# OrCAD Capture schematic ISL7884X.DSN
size B; title: ISL7884X Application Circuit Transient Test; note: <Doc>
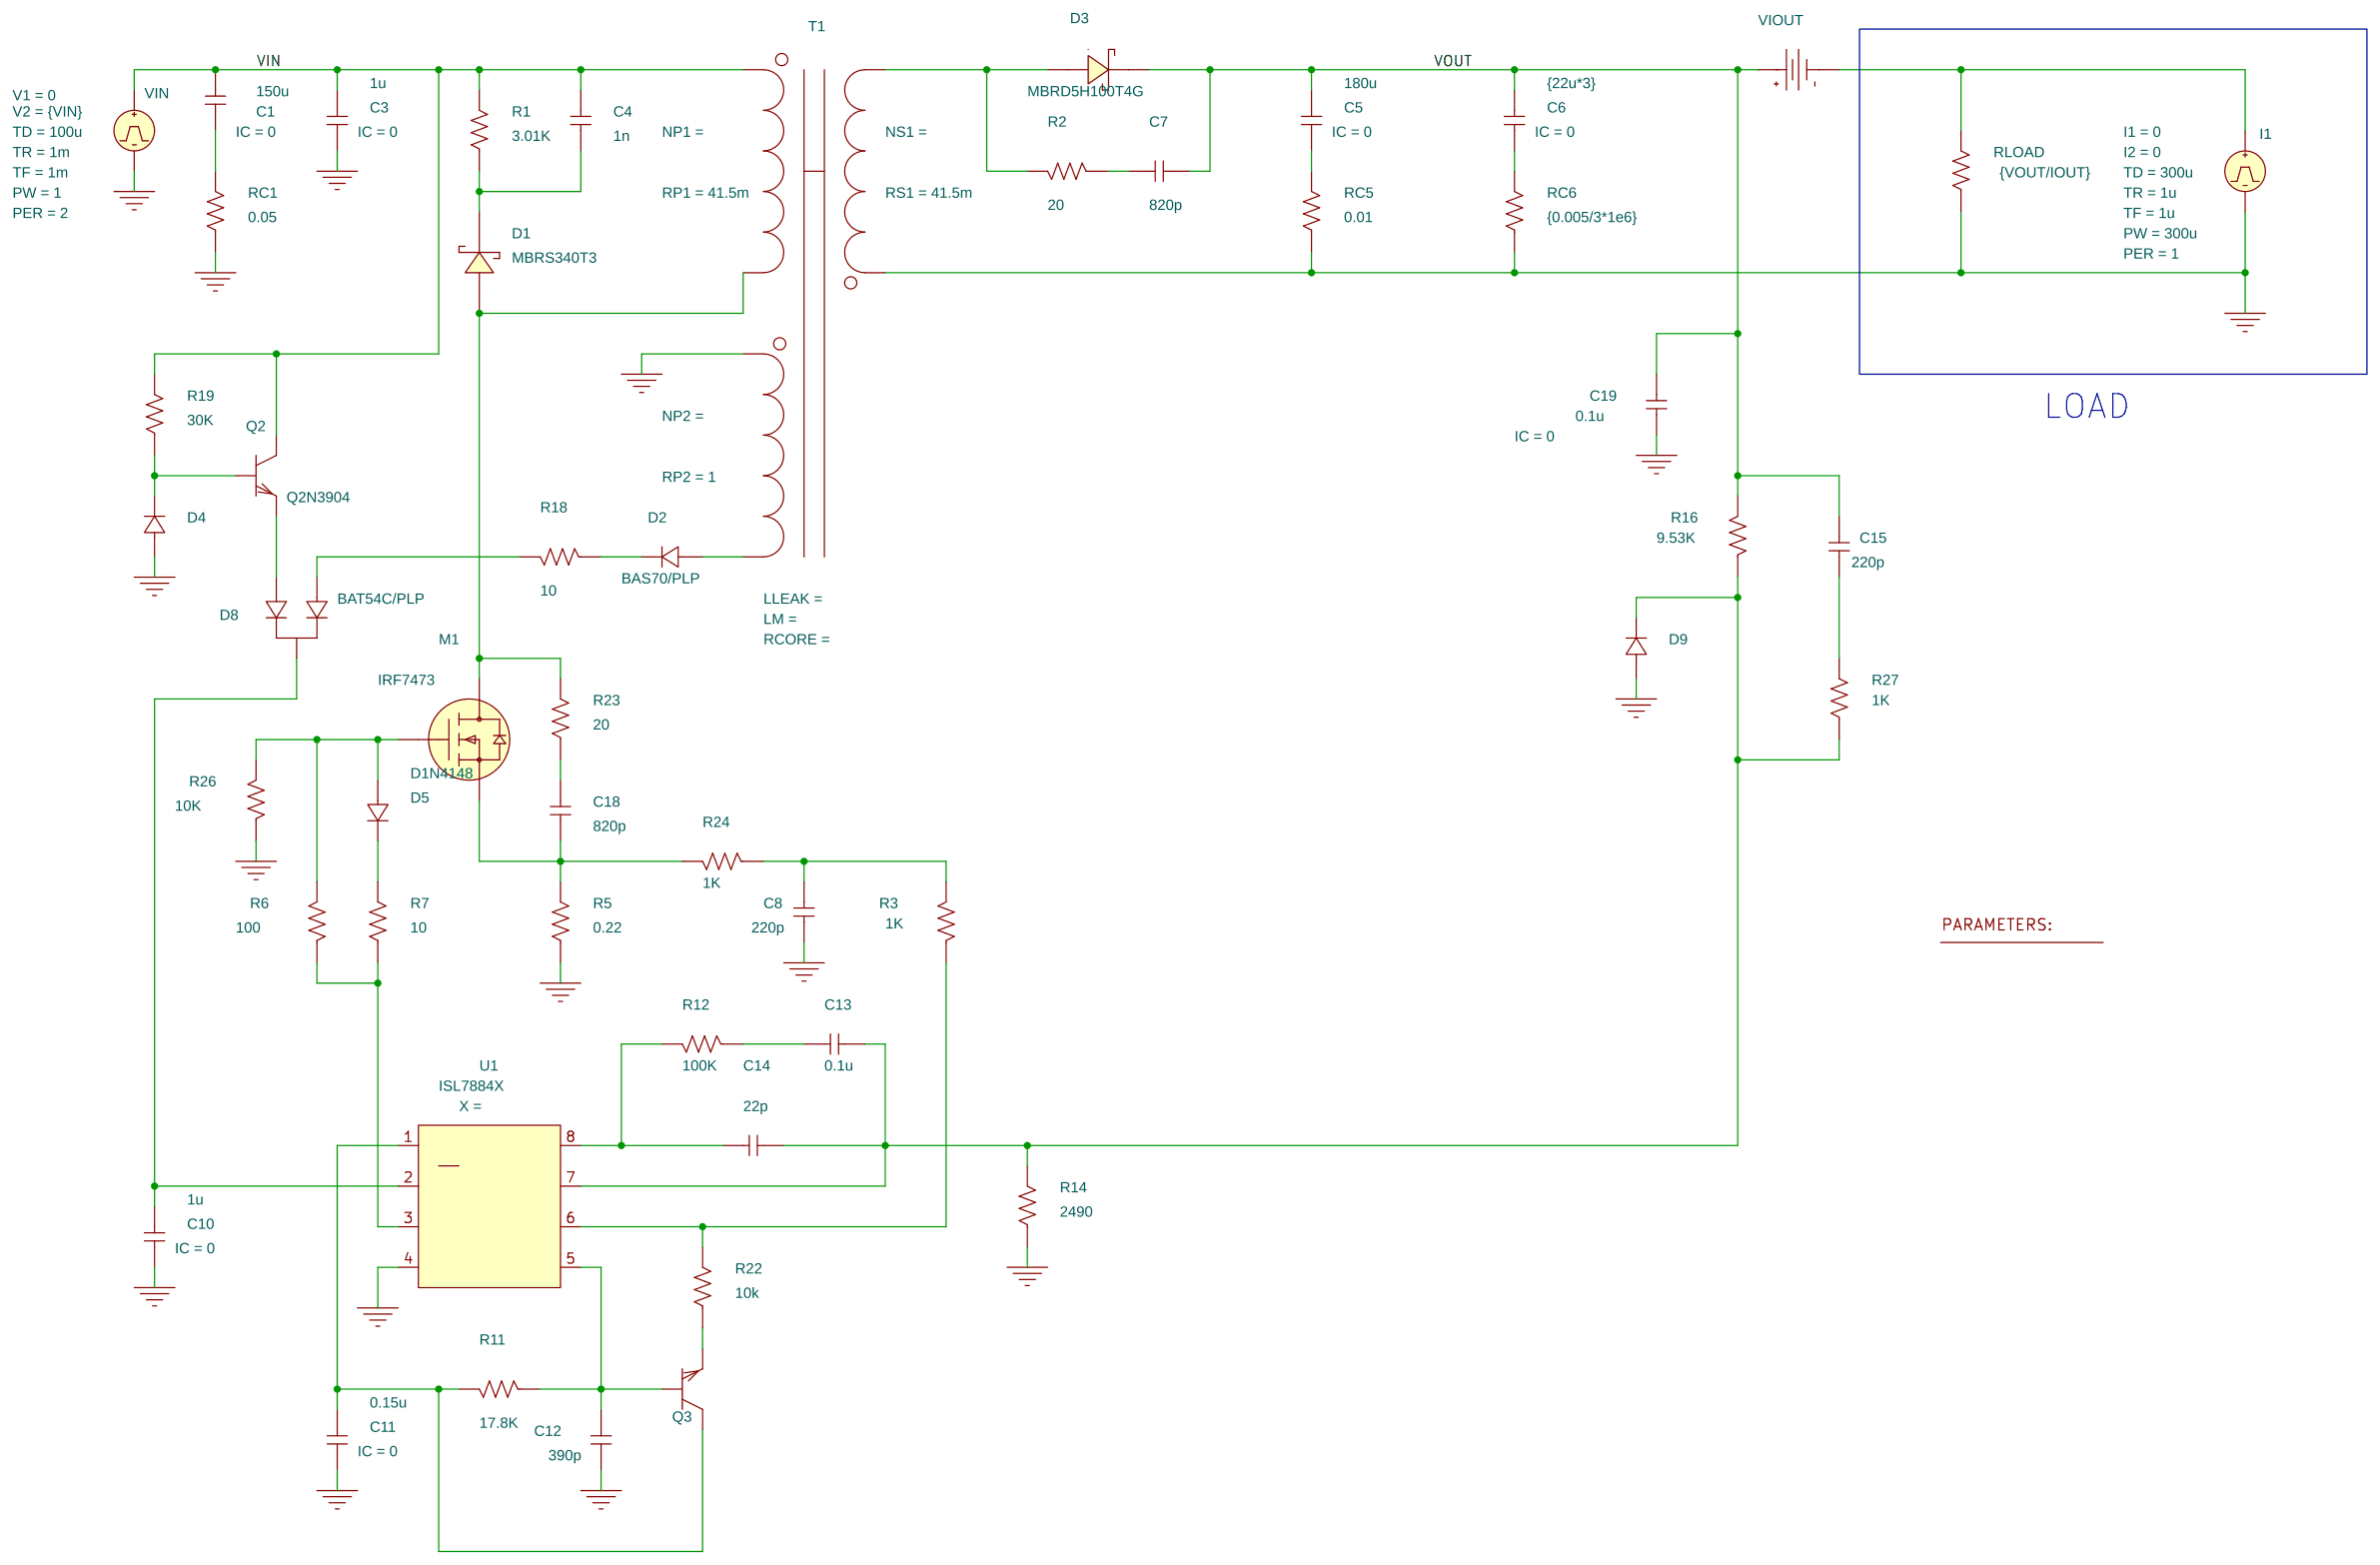
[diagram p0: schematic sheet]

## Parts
1  PARAM
C1  150u  [RAD/CK05]
C3  1u  [RAD/CK05]
C4  1n  [RAD/CK05]
C5  180u  [RAD/CK05]
C6  {22u*3}  [RAD/CK05]
C7  820p  [RAD/CK05]
C8  220p  [RAD/CK05]
C10  1u  [RAD/CK05]
C11  0.15u  [RAD/CK05]
C12  390p  [RAD/CK05]
C13  0.1u  [RAD/CK05]
C14  22p  [RAD/CK05]
C15  220p  [RAD/CK05]
C18  820p  [RAD/CK05]
C19  0.1u  [RAD/CK05]
D1  MBRS340T3  [SMC403]
D2  BAS70/PLP
D3  MBRD5H100T4G  [DPAK369C]
D4  BZX84C10V/PLP
D5  D1N4148  [DO-35]
D8  BAT54C/PLP
D9  BZX84C10V/PLP
I1  IPULSE
M1  IRF7473
Q2  Q2N3904  [TO92]
Q3  QMMBT2222ALT1/ON
R1  3.01K  [AX/RC05]
R2  20  [AX/RC05]
R3  1K  [AX/RC05]
R5  0.22  [AX/RC05]
R6  100  [AX/RC05]
R7  10  [AX/RC05]
R11  17.8K  [AX/RC05]
R12  100K  [AX/RC05]
R14  2490  [AX/RC05]
R16  9.53K  [AX/RC05]
R18  10  [AX/RC05]
R19  30K  [AX/RC05]
R22  10k  [AX/RC05]
R23  20  [AX/RC05]
R24  1K  [AX/RC05]
R26  10K  [AX/RC05]
R27  1K  [AX/RC05]
RC1  0.05  [AX/RC05]
RC5  0.01  [AX/RC05]
RC6  {0.005/3*1e6}  [AX/RC05]
RLOAD  {VOUT/IOUT}  [AX/RC05]
T1  XFOR_2P1S
U1  ISL7884X
VIN  VPULSE
VIOUT  VDC

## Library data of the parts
1 = PARAM: IOUT: 0.333; VIN: 24; VOUT: 12; X: 3
C1 C3 C5 C6 C10 C11 C19 = C: IC: 0
C4 C7 C8 C12-C15 C18 = C
D1 = MBRS340T3
D2 = BAS70_PLP
D3 = MBRD5H100T4G
D4 D9 = BZX84C10V_PLP
D5 = D1N4148
D8 = BAT54C_PLP
I1 = IPULSE: I1: 0; I2: 0; PER: 1; PW: 300u; TD: 300u; TF: 1u; TR: 1u
M1 = IRF7473
Q2 = Q2N3904
Q3 = QMMBT2222ALT1_ON
R1-R3 R5-R7 R11 R12 R14 R16 R18 R19 R22-R24 R26 R27 RC1 RC5 RC6 RLOAD = R
T1 = XFOR_2P1S: RP1: 41.5m; RP2: 1; RS1: 41.5m
U1 = ISL7884X
VIN = VPULSE: PER: 2; PW: 1; TD: 100u; TF: 1m; TR: 1m; V1: 0; V2: {VIN}
VIOUT = VDC

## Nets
VIN: C1.1 C3.1 C4.2 Q2.3(c) R1.2 R19.2 T1.1(P1A) VIN.1(+)
0: C3.2 C8.1 C10.2 C11.2 C12.1 C19.1 D4.0(1) D9.0(1) I1.2(-) R5.1 R14.1 R26.1 RC1.1 RC5.1 RC6.1 RLOAD.1 T1.4(S1A) T1.5(P2A) U1.4(GND) VIN.2(-)
VOUT: C5.1 C6.1 C7.1 C15.2 C19.2 D3.4(C) R16.2 VIOUT.0(+)
N00586: C4.1 D1.1(C) R1.1
N00761: D1.2(A) M1.5(D) R23.2 T1.2(P1B)
N00796: D2.0(1) T1.6(P2B)
N01023: C18.2 R23.1
N01027: C18.1 M1.3(S) R5.2 R24.2
N01178: D5.2 R7.2
N01182: D5.1 M1.4(G) R6.2 R26.2
N01198: R6.1 R7.1 U1.3(OUT)
N01751: D3.3(A) R2.2 T1.3(S1B)
N01782: C7.2 R2.1
N01824: D4.1(2) Q2.2(b) R19.1
N02071: D2.1(2) R18.1
N02075: C10.1 D8.0(3) Q2.1(e) R18.2 U1.2(VDD)
N02242: C5.2 RC5.2
N02445: C6.2 RC6.2
N02686: C11.1 Q3.1(c) R11.2 U1.1(VREF)
N03348: C12.2 Q3.0(b) R11.1 U1.5(RTCT)
N03558: Q3.2(e) R22.1
N03562: R3.1 R22.2 U1.6(CS)
N03647: C14.2 R12.2 U1.8(COMP)
N03664: C13.2 R12.1
N03668: C13.1 C14.1 D9.1(2) R14.2 R16.1 R27.1 U1.7(FB)
N03843: C8.2 R3.2 R24.1
N04190: I1.1(+) RLOAD.2 VIOUT.1(-)
N05515: C15.1 R27.2
N05875: C1.2 RC1.2

Not connected (* = marked no-connect by the designer): D3 1(NC)

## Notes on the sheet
- LOAD
